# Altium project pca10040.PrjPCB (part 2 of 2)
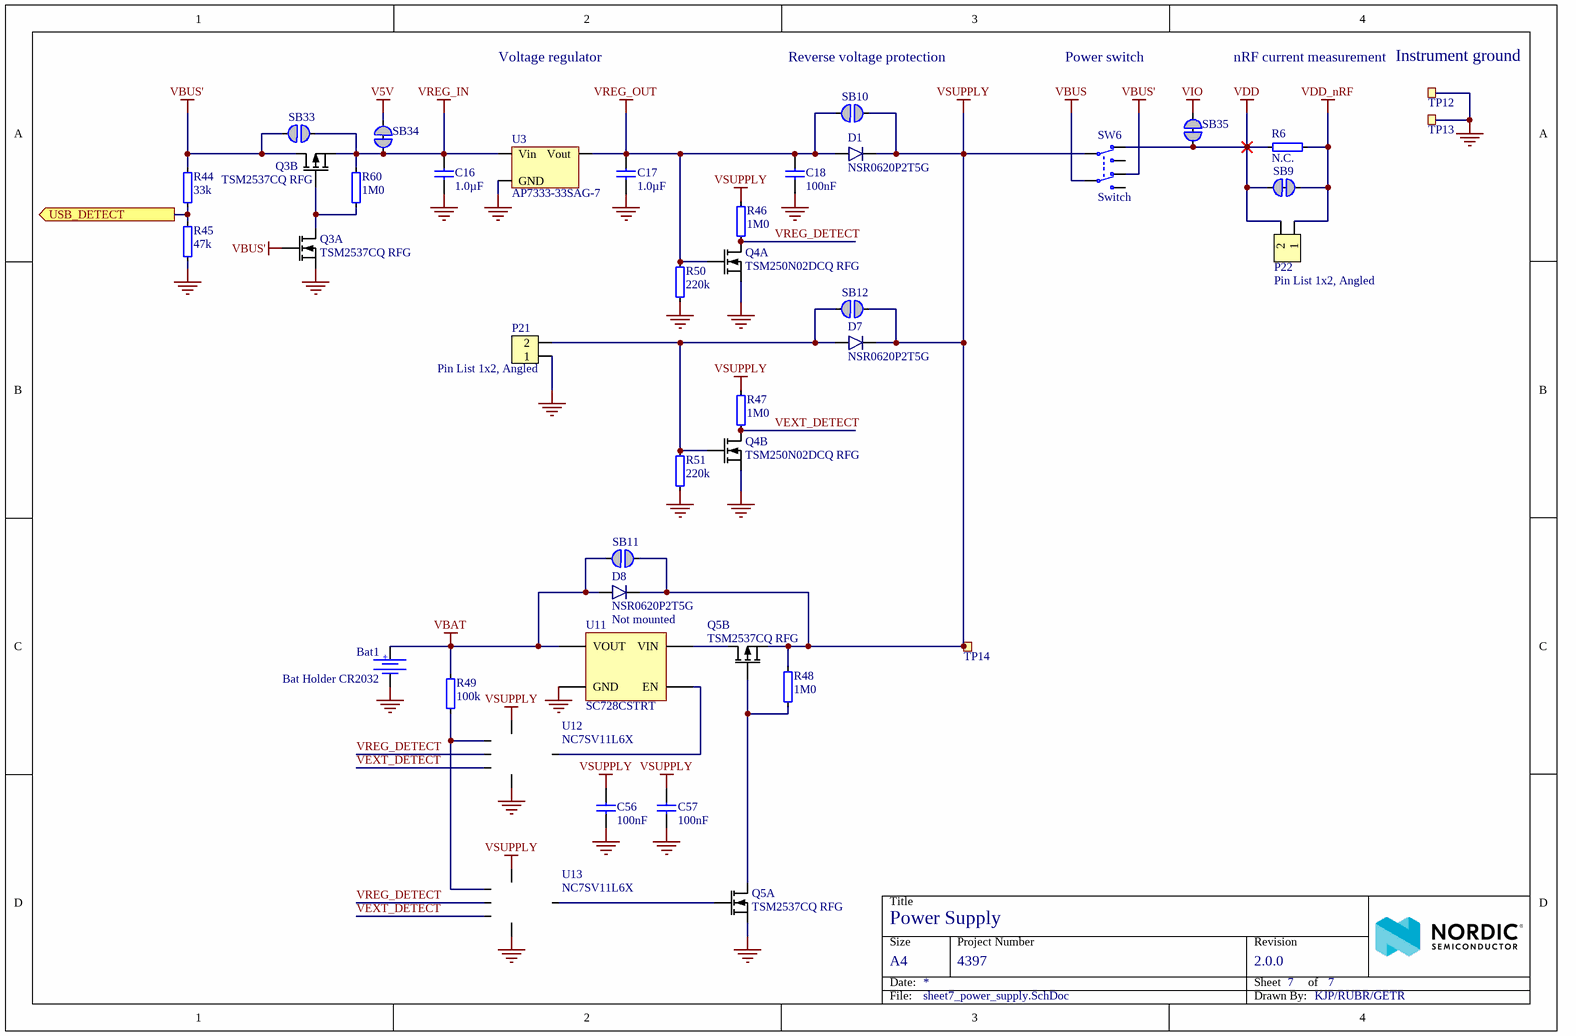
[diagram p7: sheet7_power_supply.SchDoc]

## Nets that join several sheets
GND: sheet2_radio (22 pins), sheet4_interface_mcu (44 pins), sheet5_buttons_and_leds (18 pins), sheet6_connectors (67 pins), sheet7_power_supply (20 pins)
V5V: sheet6_connectors (5 pins), sheet7_power_supply (SB34.1)
VBUS: sheet6_connectors (6 pins), sheet7_power_supply (SW6.5)
VDD: sheet4_interface_mcu (8 pins), sheet5_buttons_and_leds (11 pins), sheet6_connectors (5 pins), sheet7_power_supply (5 pins)
VDD_nRF: sheet2_radio (6 pins), sheet6_connectors (P20.1 P24.1), sheet7_power_supply (P22.1 R6.2 SB9.1)
VDD_SAM: sheet4_interface_mcu (25 pins), sheet5_buttons_and_leds (R5.2), sheet6_connectors (J3.1 R21.2 R22.2 R23.2)
VIO: sheet6_connectors (9 pins), sheet7_power_supply (SB35.1)
BOOT/RESET: sheet4_interface_mcu (SB36.2 SB42.1 U10.4), sheet5_buttons_and_leds (R5.1 SW5.2)
D17: sheet3_pin_map (SB13.1), sheet6_connectors (P6.4 P12.4 P17.8)
D18: sheet3_pin_map (SB14.1), sheet6_connectors (P6.5 P12.5 P17.10)
D19: sheet3_pin_map (SB15.1), sheet6_connectors (P6.6 P12.6 P17.12)
D20: sheet3_pin_map (SB16.1), sheet6_connectors (P6.7 P12.7 P17.14)
DFSD_N: sheet4_interface_mcu (U2.80), sheet6_connectors (R14.1)
DFSD_P: sheet4_interface_mcu (U2.81), sheet6_connectors (R13.1)
DHSD_N: sheet4_interface_mcu (U2.77), sheet6_connectors (D2.2 J2.2 R14.2 TP2.1)
DHSD_P: sheet4_interface_mcu (U2.76), sheet6_connectors (D2.3 J2.3 R13.2 TP1.1)
EXT_GND_DETECT: sheet4_interface_mcu (U2.67), sheet6_connectors (P19.9)
EXT_RESET: sheet4_interface_mcu (U2.68), sheet6_connectors (P19.10)
EXT_SWDCLK: sheet4_interface_mcu (U2.70), sheet6_connectors (P19.4)
EXT_SWDIO: sheet4_interface_mcu (U2.71), sheet6_connectors (P19.2)
EXT_SWO: sheet4_interface_mcu (U2.18), sheet6_connectors (P19.6)
EXT_VTG: sheet4_interface_mcu (Q1.4 R8.1), sheet6_connectors (P19.1 SB32.2)
IMCU_RESET: sheet4_interface_mcu (U2.57), sheet6_connectors (J3.10 R23.1)
IMCU_TCKS: sheet4_interface_mcu (U2.56), sheet6_connectors (J3.4 R22.1)
IMCU_TDIS: sheet4_interface_mcu (U2.51), sheet6_connectors (J3.8 R24.1)
IMCU_TDOS: sheet4_interface_mcu (U2.54), sheet6_connectors (J3.6)
IMCU_TMSS: sheet4_interface_mcu (U2.55), sheet6_connectors (J3.2 R21.1)
IOEXP_IRQ: sheet3_pin_map (SB30.2), sheet5_buttons_and_leds (U6.4)
P0.00: sheet2_radio (SB4.2), sheet6_connectors (P6.1 P12.1 P17.2)
P0.01: sheet2_radio (SB3.2), sheet6_connectors (P6.2 P12.2 P17.4)
P0.02: sheet2_radio (U1.4), sheet6_connectors (P4.8 P10.8 P16.16)
P0.03: sheet2_radio (U1.5), sheet6_connectors (P2.1 P8.1 P14.2)
P0.04: sheet2_radio (U1.6), sheet6_connectors (P2.2 P8.2 P14.4)
P0.05: sheet2_radio (U1.7), sheet3_pin_map (SB13.2), sheet4_interface_mcu (SB22.2)
P0.06: sheet2_radio (U1.8), sheet3_pin_map (SB14.2), sheet4_interface_mcu (SB23.2)
P0.07: sheet2_radio (U1.9), sheet3_pin_map (SB15.2), sheet4_interface_mcu (SB24.2)
P0.08: sheet2_radio (U1.10), sheet3_pin_map (SB16.2), sheet4_interface_mcu (SB25.2)
P0.09/NFC1: sheet2_radio (U1.11), sheet6_connectors (R25.2 R27.2)
P0.10/NFC2: sheet2_radio (U1.12), sheet6_connectors (R26.2 R28.2)
P0.11: sheet2_radio (U1.14), sheet6_connectors (P3.1 P9.1 P15.2)
P0.12: sheet2_radio (U1.15), sheet6_connectors (P3.2 P9.2 P15.4)
P0.13: sheet2_radio (U1.16), sheet5_buttons_and_leds (U4.15), sheet6_connectors (P3.3 P9.3 P15.6)
P0.14: sheet2_radio (U1.17), sheet5_buttons_and_leds (U4.3), sheet6_connectors (P3.4 P9.4 P15.8)
P0.15: sheet2_radio (U1.18), sheet5_buttons_and_leds (U4.7), sheet6_connectors (P3.5 P9.5 P15.10)
P0.16: sheet2_radio (U1.19), sheet5_buttons_and_leds (U4.11), sheet6_connectors (P3.6 P9.6 P15.12)
P0.17: sheet2_radio (U1.20), sheet3_pin_map (SB30.1), sheet5_buttons_and_leds (U5.15), sheet6_connectors (P3.7 P9.7 P15.14)
P0.18: sheet2_radio (U1.21), sheet4_interface_mcu (SB27.2), sheet5_buttons_and_leds (U5.3), sheet6_connectors (P3.8 P9.8 P15.16 P18.6)
P0.19: sheet2_radio (U1.22), sheet5_buttons_and_leds (U5.7), sheet6_connectors (P4.1 P10.1 P16.2)
P0.20: sheet2_radio (U1.23), sheet5_buttons_and_leds (U5.11), sheet6_connectors (P4.2 P10.2 P16.4)
P0.21: sheet2_radio (U1.24), sheet3_pin_map (SB17.2 TP11.1), sheet4_interface_mcu (SB26.2 SB41.2 SB43.2 SB44.2), sheet6_connectors (P6.3 P12.3 P17.6 P18.10)
P0.22: sheet2_radio (U1.27), sheet6_connectors (P4.3 P10.3 P16.6)
P0.23: sheet2_radio (U1.28), sheet6_connectors (5 pins)
P0.24: sheet2_radio (U1.29), sheet6_connectors (5 pins)
P0.25: sheet2_radio (C52.1 U1.37), sheet6_connectors (5 pins)
P0.26: sheet2_radio (C53.1 U1.38), sheet5_buttons_and_leds (U6.12), sheet6_connectors (P4.9 P10.9 P16.18)
P0.27: sheet2_radio (U1.39), sheet5_buttons_and_leds (U6.8), sheet6_connectors (P4.10 P10.10 P16.20)
P0.28: sheet2_radio (U1.40), sheet6_connectors (P2.3 P8.3 P14.6)
P0.29: sheet2_radio (U1.41), sheet6_connectors (P2.4 P8.4 P14.8)
P0.30: sheet2_radio (U1.42), sheet6_connectors (P2.5 P8.5 P14.10)
P0.31: sheet2_radio (U1.43), sheet6_connectors (P2.6 P8.6 P14.12)
RESET_PIN: sheet3_pin_map (SB17.1), sheet4_interface_mcu (SB42.2 SB43.1 U10.8), sheet6_connectors (5 pins)
SH_GND_DETECT: sheet4_interface_mcu (U2.62), sheet6_connectors (P20.8 P24.8)
SH_RESET: sheet4_interface_mcu (U2.63), sheet6_connectors (P20.7 P24.7)
SH_SWDCLK: sheet4_interface_mcu (U2.65), sheet6_connectors (P20.5 P24.5)
SH_SWDIO: sheet4_interface_mcu (U2.66), sheet6_connectors (P20.4 P24.4)
SH_SWO: sheet4_interface_mcu (U2.21), sheet6_connectors (P20.6 P24.6)
SH_VTG: sheet4_interface_mcu (Q2.4 R9.1), sheet6_connectors (P20.3 P24.3)
SHIELD_DETECT: sheet5_buttons_and_leds (U4.2 U5.2 U6.2), sheet6_connectors (R39.1 SB19.2 TP15.1)
SWDCLK: sheet2_radio (U1.25), sheet4_interface_mcu (SB21.2), sheet6_connectors (P18.4)
SWDIO: sheet2_radio (U1.26), sheet4_interface_mcu (SB20.2), sheet6_connectors (P18.2)
USB_DETECT: sheet4_interface_mcu (8 pins), sheet7_power_supply (R44.2 R45.1)

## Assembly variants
Variant of pca10040: not fitted C1 C2 C3 C4 C5 C6 C7 C8 C9 C10 C11 C12 C13 C14 C15 C16 C17 C18 C19 C20 C21 C22 C23 C24 C25 C26 C27 C28 C29 C30 C31 C32 C33 C34 C35 C36 C37 C38 C39 C40 C41 C42 C43 C44 C45 C46 C47 C48 C49 C50 C51 C52 C53 C54 C55 D2 D3 D4 D5 D6 D8 Fid1 Fid2 L1 L2 L3 Q1 Q2 R1 R2 R3 R4 R5 R6 R8 R9 R10 R11 R12 R13 R14 R15 R16 R17 R19 R20 R21 R22 R23 R24 R25 R26 R27 R28 R29 R30 R31 R32 R33 R34 R35 R36 R37 R38 R39 R40 R41 R42 R43 R46 R60 U3 U4 U5 U6 U7 X1 X2 X3
Variant of pca10040_Airfuel: not fitted Fid1 Fid2 P13 P14 P15 P16 P17 R7 R18 R46 R48 R52 R53 R54 R55 R56 R57 R58 R59 R60; alternate parts C14 -> C0402-100n, C54 -> C0402-100n, C55 -> C0402-100n, U10 -> NX3DV2567GU, U8 -> FSA2466UMX, U9 -> FSA2466UMX, P7 -> Pin List 1x8 SMD, P8 -> Pin List 1x6 SMD, P9 -> Pin List 1x8 SMD, P10 -> Pin List 1x10 SMD, P11 -> Socket 2x3 SMD Bottom, P12 -> Pin List 1x9 SMD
